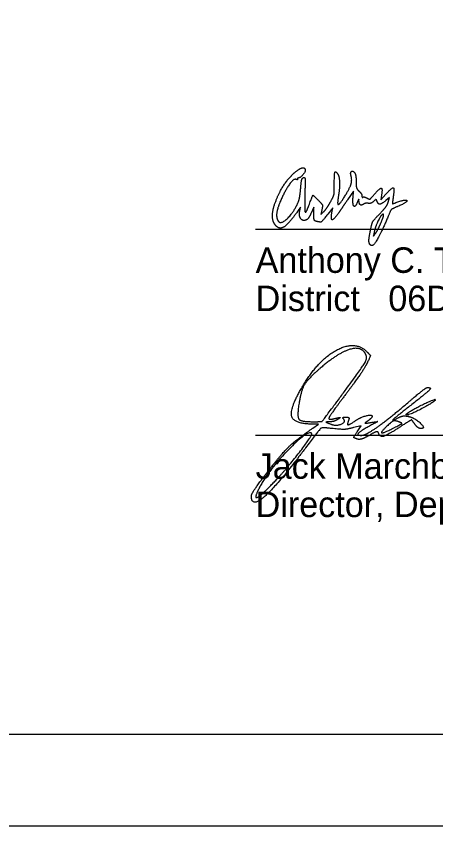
# Model space of a CAD drawing. Extents: x 0 to 34, y 0 to 22.
# Drawn here: x 23.213 to 25.517, y 0 to 4.44 of the extents above; entities that cross this region are included whole.
import ezdxf

# ---------------------------------------------------------------- set-up
doc = ezdxf.new("R2010")
doc.units = 0
for name, color, linetype in [('SH_Border', 7, 'Continuous'), ('SH_Cut_Line', 7, 'Continuous'), ('SH_Data', 7, 'Continuous'), ('SH_Text', 7, 'Continuous')]:
    doc.layers.add(name, color=color, linetype=linetype)

msp = doc.modelspace()

# ---------------------------------------------------------------- linework, layer by layer
at = {"layer": 'SH_Border'}
msp.add_lwpolyline([(1.5, 21.5), (33.5, 21.5), (33.5, 0.5), (1.5, 0.5)], close=True, dxfattribs=at)
at = {"layer": 'SH_Cut_Line'}
msp.add_lwpolyline([(0, 0), (34, 0), (34, 22), (0, 22)], close=True, dxfattribs=at)
at = {"layer": 'SH_Data'}
for p, q in [((24.5279, 3.2725), (28.0279, 3.2725)), ((24.5279, 2.1431), (28.0279, 2.1431))]:
    msp.add_line(p, q, dxfattribs=at)
at = {"layer": 'SH_Text'}
for p, q in [((25.2156, 3.3068), (25.2156, 3.3068)), ((25.157, 3.1858), (25.157, 3.1858)), ((24.9902, 2.3481), (24.9902, 2.3481)), ((25.3555, 2.2583), (25.3555, 2.2583)), ((25.3107, 2.2166), (25.3107, 2.2166))]:
    msp.add_line(p, q, dxfattribs=at)
for points in [[(25.0623, 3.4452), (25.0648, 3.4806), (25.032, 3.4326)], [(25.2187, 3.4583), (25.2144, 3.4326), (25.2425, 3.4634)], [(25.2556, 3.4209), (25.2625, 3.445), (25.2419, 3.4288)], [(24.7697, 3.3702), (24.774, 3.3923), (24.757, 3.3684)], [(24.8473, 3.3555), (24.8471, 3.3926), (24.8322, 3.3598)], [(24.8914, 3.3789), (24.8859, 3.3526), (24.902, 3.3686)], [(24.946, 3.3612), (24.9507, 3.3898), (24.9233, 3.354)], [(24.8425, 2.1812), (24.8732, 2.2024), (24.8354, 2.2031)], [(25.0855, 2.1613), (25.1067, 2.1937), (25.0649, 2.1836)]]:
    msp.add_lwpolyline(points, dxfattribs=at)
for points in [[(24.7437, 3.5835), (24.7705, 3.6061), (24.7995, 3.6115), (24.7995, 3.5938)], [(24.6396, 3.4289), (24.6598, 3.4802), (24.7107, 3.5558), (24.7437, 3.5835)], [(24.7606, 3.5526), (24.7578, 3.5526), (24.7563, 3.55), (24.7574, 3.5469)], [(24.7995, 3.5938), (24.7995, 3.5832), (24.7707, 3.5526), (24.7606, 3.5526)], [(24.775, 3.496), (24.7778, 3.5312), (24.7833, 3.5526), (24.79, 3.5548)], [(24.79, 3.5548), (24.7983, 3.5576), (24.7999, 3.5385), (24.798, 3.4614)], [(24.9595, 3.5201), (24.9595, 3.5761), (24.9665, 3.5936), (24.9801, 3.5717)], [(24.9801, 3.5717), (24.9876, 3.5595), (24.9892, 3.4952), (24.983, 3.4592)], [(25.015, 3.4491), (25.0431, 3.4935), (25.0586, 3.5422), (25.0516, 3.5643)], [(25.0516, 3.5643), (25.0458, 3.5826), (25.0625, 3.595), (25.0723, 3.5796)], [(25.0723, 3.5796), (25.0761, 3.5736), (25.0793, 3.5521), (25.0794, 3.5318)], [(24.7485, 3.5453), (24.7359, 3.5502), (24.6881, 3.4819), (24.6629, 3.4233)], [(24.7574, 3.5469), (24.7584, 3.5437), (24.7544, 3.543), (24.7485, 3.5453)], [(24.9388, 3.4221), (24.9559, 3.4532), (24.9595, 3.4701), (24.9595, 3.5201)], [(25.0794, 3.5318), (25.0795, 3.5053), (25.084, 3.491), (25.0955, 3.4806)], [(24.7618, 3.4206), (24.7666, 3.4316), (24.7725, 3.4655), (24.775, 3.496)], [(25.0955, 3.4806), (25.1043, 3.4726), (25.1115, 3.4607), (25.1115, 3.454)], [(25.1382, 3.4432), (25.1526, 3.4355), (25.1582, 3.4383), (25.1806, 3.4642)], [(25.1806, 3.4642), (25.2101, 3.4983), (25.225, 3.4959), (25.2187, 3.4583)], [(25.2425, 3.4634), (25.2773, 3.5016), (25.2902, 3.4962), (25.2828, 3.4466)], [(24.6342, 3.2969), (24.6185, 3.3185), (24.6211, 3.382), (24.6396, 3.4289)], [(24.6629, 3.4233), (24.6464, 3.3848), (24.6408, 3.3339), (24.6511, 3.3172)], [(24.6511, 3.3172), (24.6644, 3.2957), (24.7369, 3.3635), (24.7618, 3.4206)], [(24.798, 3.4614), (24.7966, 3.4081), (24.7979, 3.3646), (24.8008, 3.3646)], [(24.8201, 3.4026), (24.8401, 3.4569), (24.8441, 3.4591), (24.8721, 3.4304)], [(24.8721, 3.4304), (24.8933, 3.4088), (24.8961, 3.4013), (24.8914, 3.3789)], [(24.902, 3.3686), (24.9109, 3.3774), (24.9275, 3.4015), (24.9388, 3.4221)], [(24.983, 3.4592), (24.9743, 3.4096), (24.9874, 3.4055), (25.015, 3.4491)], [(25.032, 3.4326), (25.0139, 3.4062), (24.9911, 3.373), (24.9813, 3.3589)], [(25.087, 3.4219), (25.0747, 3.3912), (25.0596, 3.4055), (25.0623, 3.4452)], [(25.095, 3.4271), (25.0946, 3.4366), (25.0922, 3.435), (25.087, 3.4219)], [(25.1215, 3.4099), (25.1084, 3.4017), (25.0956, 3.41), (25.095, 3.4271)], [(25.1115, 3.454), (25.1115, 3.4474), (25.1138, 3.4442), (25.1165, 3.447)], [(25.1165, 3.447), (25.1193, 3.4498), (25.1291, 3.448), (25.1382, 3.4432)], [(25.1752, 3.4243), (25.1673, 3.4172), (25.1542, 3.4125), (25.1462, 3.4138)], [(25.1942, 3.4249), (25.19, 3.436), (25.188, 3.4359), (25.1752, 3.4243)], [(25.2419, 3.4288), (25.2173, 3.4095), (25.2007, 3.4081), (25.1942, 3.4249)], [(25.2086, 3.3562), (25.2307, 3.3786), (25.2518, 3.4077), (25.2556, 3.4209)], [(25.2828, 3.4466), (25.2779, 3.414), (25.2788, 3.4106), (25.2911, 3.4154)], [(25.2911, 3.4154), (25.3506, 3.4382), (25.365, 3.4212), (25.3071, 3.3964)], [(24.8008, 3.3646), (24.8038, 3.3646), (24.8125, 3.3817), (24.8201, 3.4026)], [(25.1462, 3.4138), (25.1381, 3.4151), (25.127, 3.4134), (25.1215, 3.4099)], [(25.3071, 3.3964), (25.2757, 3.383), (25.2684, 3.3751), (25.2535, 3.3387)], [(24.757, 3.3684), (24.7073, 3.2986), (24.6552, 3.2683), (24.6342, 3.2969)], [(24.8052, 3.3224), (24.7863, 3.3151), (24.7648, 3.3442), (24.7697, 3.3702)], [(24.8322, 3.3598), (24.8241, 3.3418), (24.8119, 3.3249), (24.8052, 3.3224)], [(24.8615, 3.3148), (24.8507, 3.3176), (24.8474, 3.327), (24.8473, 3.3555)], [(24.9233, 3.354), (24.894, 3.3156), (24.8837, 3.3091), (24.8615, 3.3148)], [(24.9813, 3.3589), (24.9565, 3.3232), (24.94, 3.3242), (24.946, 3.3612)], [(25.16, 3.2757), (25.1667, 3.3068), (25.1773, 3.3244), (25.2086, 3.3562)], [(25.2535, 3.3387), (25.2283, 3.277), (25.1799, 3.1861), (25.1705, 3.183)], [(25.2295, 3.3532), (25.2229, 3.3599), (25.1859, 3.2911), (25.1798, 3.2606)], [(25.2156, 3.3068), (25.2255, 3.3301), (25.2318, 3.3509), (25.2295, 3.3532)], [(25.1858, 3.2486), (25.1922, 3.2574), (25.2056, 3.2836), (25.2156, 3.3068)], [(25.157, 3.1858), (25.149, 3.1937), (25.1502, 3.23), (25.16, 3.2757)], [(25.1798, 3.2606), (25.1745, 3.2347), (25.175, 3.2338), (25.1858, 3.2486)], [(25.1705, 3.183), (25.1661, 3.1815), (25.16, 3.1827), (25.157, 3.1858)], [(24.7789, 2.3989), (24.8651, 2.5493), (25.0732, 2.6653), (25.1389, 2.5997)], [(25.1299, 2.5905), (25.104, 2.6325), (24.9779, 2.5913), (24.8825, 2.5097)], [(24.9902, 2.3481), (25.1115, 2.5116), (25.144, 2.5678), (25.1299, 2.5905)], [(25.1389, 2.5997), (25.1577, 2.5809), (25.1577, 2.5758), (25.1394, 2.5374)], [(25.1394, 2.5374), (25.1284, 2.5144), (25.0767, 2.4389), (25.0245, 2.3695)], [(24.8825, 2.5097), (24.8159, 2.4527), (24.7771, 2.3886), (24.766, 2.3173)], [(24.8354, 2.2031), (24.7375, 2.2048), (24.7141, 2.2859), (24.7789, 2.3989)], [(25.369, 2.3254), (25.4194, 2.3683), (25.4649, 2.4034), (25.4701, 2.4035)], [(25.4701, 2.4035), (25.495, 2.404), (25.4716, 2.3785), (25.3857, 2.3112)], [(25.0245, 2.3695), (24.9722, 2.3001), (24.9295, 2.2395), (24.9295, 2.2347)], [(24.766, 2.3173), (24.7545, 2.2439), (24.776, 2.2162), (24.844, 2.2162)], [(24.844, 2.2162), (24.8907, 2.2162), (24.8953, 2.2203), (24.9902, 2.3481)], [(25.1076, 2.1412), (25.1307, 2.1412), (25.2567, 2.23), (25.369, 2.3254)], [(25.3857, 2.3112), (25.2925, 2.2382), (25.271, 2.2167), (25.315, 2.2402)], [(25.3555, 2.2583), (25.3759, 2.2761), (25.5079, 2.3419), (25.5131, 2.3368)], [(25.5131, 2.3368), (25.5193, 2.3306), (25.3767, 2.2537), (25.359, 2.2537)], [(24.9295, 2.2347), (24.9295, 2.2299), (24.9449, 2.2296), (24.9638, 2.234)], [(24.9795, 2.2293), (24.9692, 2.2223), (24.9495, 2.2162), (24.9357, 2.2156)], [(24.9399, 2.203), (24.9698, 2.191), (25.026, 2.2156), (25.0086, 2.233)], [(24.9638, 2.234), (24.9894, 2.2399), (24.9934, 2.2387), (24.9795, 2.2293)], [(25.0086, 2.233), (25.004, 2.2375), (25.0103, 2.2412), (25.0225, 2.2412)], [(25.0225, 2.2412), (25.037, 2.2412), (25.0422, 2.2348), (25.0375, 2.2225)], [(25.0375, 2.2225), (25.0285, 2.1992), (25.0414, 2.1986), (25.0736, 2.2206)], [(25.0736, 2.2206), (25.1025, 2.2404), (25.167, 2.2579), (25.167, 2.246)], [(25.1453, 2.2219), (25.1264, 2.2081), (25.1284, 2.2068), (25.161, 2.2117)], [(25.167, 2.246), (25.167, 2.2414), (25.1572, 2.2306), (25.1453, 2.2219)], [(25.3107, 2.2166), (25.2935, 2.223), (25.277, 2.2178), (25.2576, 2.2001)], [(25.315, 2.2402), (25.3276, 2.2469), (25.3515, 2.249), (25.3681, 2.2448)], [(25.4011, 2.2034), (25.3843, 2.2275), (25.3822, 2.227), (25.3165, 2.1846)], [(25.359, 2.2537), (25.3542, 2.2537), (25.3526, 2.2558), (25.3555, 2.2583)], [(25.3681, 2.2448), (25.4042, 2.2357), (25.4625, 2.1787), (25.4358, 2.1787)], [(24.5916, 1.939), (24.6692, 2.0395), (24.7493, 2.1168), (24.8425, 2.1812)], [(24.9237, 2.1813), (24.8903, 2.1846), (24.8786, 2.1741), (24.8019, 2.0725)], [(24.9357, 2.2156), (24.9133, 2.2147), (24.9138, 2.2134), (24.9399, 2.203)], [(25.0649, 2.1836), (25.0246, 2.1739), (25.0023, 2.1735), (24.9237, 2.1813)], [(25.1522, 2.1919), (25.1011, 2.1637), (25.0814, 2.1412), (25.1076, 2.1412)], [(25.161, 2.2117), (25.1977, 2.2173), (25.1976, 2.217), (25.1522, 2.1919)], [(25.3165, 2.1846), (25.2476, 2.1403), (25.2101, 2.1306), (25.202, 2.1549)], [(25.2576, 2.2001), (25.2133, 2.1596), (25.2246, 2.1507), (25.2826, 2.1803)], [(25.2826, 2.1803), (25.329, 2.204), (25.3325, 2.2086), (25.3107, 2.2166)], [(25.4358, 2.1787), (25.4262, 2.1787), (25.4106, 2.1898), (25.4011, 2.2034)], [(24.8354, 2.152), (24.8145, 2.1729), (24.596, 1.9472), (24.5497, 1.8569)], [(24.6198, 1.8756), (24.6874, 1.9447), (24.8431, 2.1443), (24.8354, 2.152)], [(25.0843, 2.1213), (25.0661, 2.1283), (25.0662, 2.1319), (25.0855, 2.1613)], [(25.1508, 2.1411), (25.1252, 2.126), (25.0953, 2.1171), (25.0843, 2.1213)], [(25.202, 2.1549), (25.1991, 2.1635), (25.1799, 2.1583), (25.1508, 2.1411)], [(24.8019, 2.0725), (24.6496, 1.8704), (24.5045, 1.7418), (24.5045, 1.8088)], [(24.5045, 1.8088), (24.5045, 1.8184), (24.5437, 1.877), (24.5916, 1.939)], [(24.5497, 1.8569), (24.5184, 1.7959), (24.55, 1.8044), (24.6198, 1.8756)]]:
    msp.add_open_spline(points, degree=2, dxfattribs=at)

# ---------------------------------------------------------------- texts
for s, p in [('Anthony C. Turowski, P.E.', (24.5279, 3.0325)), ('District       Deputy Director', (24.5279, 2.8225)), ('              06', (24.5279, 2.8225)), ('Jack Marchbanks, PhD', (24.5279, 1.9031)), ('Director, Department of Transportation', (24.5279, 1.6931))]:
    msp.add_text(s, height=0.14, dxfattribs=at).set_placement(p)

doc.saveas('drawing.dxf')
